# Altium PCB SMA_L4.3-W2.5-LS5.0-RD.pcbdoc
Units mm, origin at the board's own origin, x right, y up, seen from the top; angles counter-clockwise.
Board outline 18.91 x 15.65 mm, 2 copper layers (Top Layer, Bottom Layer), stack 0 mm thick; 1 components, 0 nets, 2 pads, 0 vias.
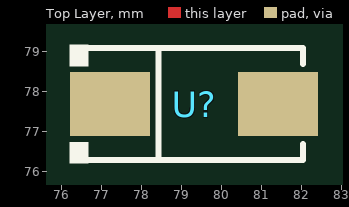
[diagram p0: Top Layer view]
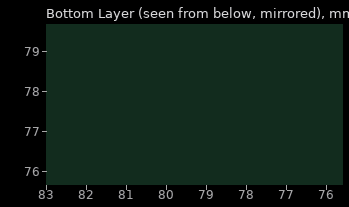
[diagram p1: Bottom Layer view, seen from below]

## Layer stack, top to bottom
Top Layer: signal copper (thickness not stored)
Bottom Layer: signal copper (thickness not stored)

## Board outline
88.757,69.85 69.85,69.85 69.85,85.505 88.757,85.505

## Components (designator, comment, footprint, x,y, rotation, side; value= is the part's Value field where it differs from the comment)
U? "" SMA_L4.3-W2.5-LS5.0-RD 79.307,77.677 r0 top

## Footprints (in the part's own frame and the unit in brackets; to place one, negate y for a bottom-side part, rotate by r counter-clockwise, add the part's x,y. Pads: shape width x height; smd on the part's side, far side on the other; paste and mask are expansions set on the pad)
SMA_L4.3-W2.5-LS5.0-RD [mm]
  rect 2x1.593 smd: 1(-2.1,0) 2(2.1,0)
  silkscreen extent -3.11,-1.48 2.73,1.48

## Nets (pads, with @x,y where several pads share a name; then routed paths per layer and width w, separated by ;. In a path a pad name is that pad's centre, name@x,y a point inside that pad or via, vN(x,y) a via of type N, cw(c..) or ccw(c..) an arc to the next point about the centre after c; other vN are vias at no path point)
pads on no net: U?.1 U?.2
